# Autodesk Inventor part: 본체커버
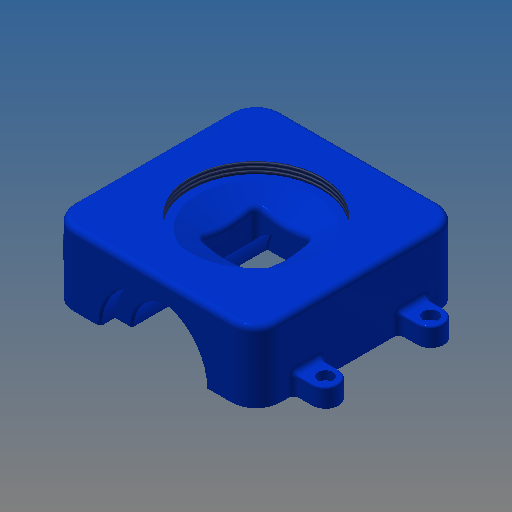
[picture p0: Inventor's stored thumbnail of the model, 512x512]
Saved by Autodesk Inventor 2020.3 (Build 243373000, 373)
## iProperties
Created: 2018-01
Part Number: 본체커버
Material: 알루미늄 6061
Document SubType Name: Modeling
Designer: mduedu
Density: 1 g/cm^3
Appearance: 선명 - 파란색
Author: mduedu
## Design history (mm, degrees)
sketch "스케치1"
  geometry: L1 (55, 55)-(-55, 55); L2 (-55, 55)-(-55, -55); L3 (-55, -55)-(55, -55); L4 (55, -55)-(55, 55); L5 (55, 55)-(-55, -55); L6 (-55, 55)-(55, -55); 1 further point
  constraints: 12 end point, 2 midpoint, 2 parallel, 1 horizontal, 1 perpendicular
  dimensions: "d0" = 110 distance of L3.end L2.end; "d1" = 110 distance of L2.end L1.end
extrude "돌출1" new body sketch "스케치1" distance "d2" = 38; taper "d3" = 0 deg
revolve "회전1" stored, may be unused: angle "d13" = 90 deg
fillet "모깎기1" dims "d14" = 1
fillet "모깎기2" dims "d15" = 13
fillet "모깎기3" dims "d16" = 3
sketch "스케치3"
  geometry: L1 (-15, -15)-(15, -15); L2 (15, -15)-(15, 15); L3 (15, 15)-(-15, 15); L4 (-15, 15)-(-15, -15); L5 (42, 55)-(-42, 55) reference; L6 (-15, -15)-(15, 15); L7 (15, -15)-(-15, 15); 2 further points
  constraints: 12 end point, 2 parallel, 1 horizontal, 1 midpoint, 1 perpendicular, 1 vertical alignment
  dimensions: "d19" = 30 distance of L3.end L1.start; "d20" = 30 distance between parallel lines of L2 L4; "d65" = 40 distance between parallel lines of L5 L3
extrude "돌출2" cut sketch "스케치3" extent not by distance; stored distance "d21" = 38; taper "d22" = 0 deg
fillet "모깎기4" dims "d23" = 3
sketch "스케치4"
  geometry: L1 (38, 35)-(32, 35); L2 (32, 35)-(32, 31); L3 (32, 31)-(25, 15); L4 (25, 15)-(25, 0); L5 (25, 0)-(38, 0); L6 (38, 0)-(38, 35); L7 (38, 42)-(38, -42) reference; 1 further point
  constraints: 12 end point, 2 parallel, 1 collinear, 1 horizontal, 1 horizontal alignment, 1 perpendicular
  dimensions: "d24" = 6 distance of L1.start L1.end; "d26" = 70 diameter of L1 L5; "d28" = 62 diameter of L2.end L5; "d29" = 30 diameter of L3.end L5; "d30" = 7 horizontal distance of L2.end L3.end
revolve "회전2" sketch "스케치4" stored, may be unused: angle "d31" = 90 deg
feature "스레드1" dims "d74" = 10, "d75" = 0
chamfer "모따기2" distance "d36" = 1; stored, may be unused: second distance "d37" = 2, angle "d38" = 45 deg
sketch "스케치5"
  geometry: L1 (-42, 55)-(-29, 55) reference; L2 (-55, -42)-(-55, 42) reference; L3 (42, -55)-(-42, -55) reference; L4 (55, 42)-(55, -42) reference; L5 (55, 35)-(65, 35); L6 (65, 21)-(55, 21); L7 (55, 21)-(55, 35); L8 (55, 42)-(55, -42) reference; L9 (28, 54)-(28, 47) reference; L10 (28, 47)-(20, 47) reference; L11 (19, 46)-(19, -24) reference; L12 (18, -25)-(7.5, -25) reference; L13 (7.5, -25)-(5.479, -28.5) reference; L14 (4.613, -29)-(-4.613, -29) reference; L15 (-5.479, -28.5)-(-7.5, -25) reference; L16 (-7.5, -25)-(-18, -25) reference; L17 (-19, -24)-(-19, 46) reference; L18 (-20, 47)-(-28, 47) reference; L19 (-28, 47)-(-28, 54) reference; L20 (19, 46)-(20, 47) reference; L21 (-20, 47)-(-19, 46) reference; L22 (-29, 55)-(-28, 54) reference; L23 (29, 55)-(42, 55) reference; L24 (28, 54)-(29, 55) reference; A1 r 13 centre (-42, 42) between (-42, 55) and (-55, 42) reference; A2 r 13 centre (-42, -42) between (-55, -42) and (-42, -55) reference; A3 r 13 centre (42, -42) between (42, -55) and (55, -42) reference; A4 r 13 centre (42, 42) between (55, 42) and (42, 55) reference; A5 r 7 centre (65, 28) between (65, 21) and (65, 35); A6 r 1 centre (18, -24) between (18, -25) and (19, -24) reference; A7 r 1 centre (4.613, -28) between (4.613, -29) and (5.479, -28.5) reference; A8 r 1 centre (-4.613, -28) between (-5.479, -28.5) and (-4.613, -29) reference; A9 r 1 centre (-18, -24) between (-19, -24) and (-18, -25) reference; 1 further point
  constraints: 6 end point, 2 point on circle, 2 tangent, 1 centre point, 1 collinear, 1 horizontal, 1 parallel, 1 point on line
  dimensions: "d39" = 14 distance between parallel lines of L6 L5; "d41" = 28 vertical distance of A5.centre point (0, 0); "d42" = 10 distance from line of A5.centre L4
extrude "돌출3" join sketch "스케치5" distance "d43" = 10; taper "d44" = 0 deg
fillet "모깎기6" dims "d45" = 1
fillet "모깎기7" dims "d46" = 3
sketch "스케치6"
  geometry: A1 r 7 centre (-65, 28) between (-65, 35) and (-65, 21) reference; A2 r 7 centre (-65, -28) between (-65, -21) and (-65, -35) reference; A3 r 7 centre (65, -28) between (65, -35) and (65, -21) reference; A4 r 7 centre (65, 28) between (65, 21) and (65, 35) reference; 5 further points
  constraints: 4 coincident
sketch "스케치7"
  geometry: 4 further points
  constraints: 4 other
hole "구멍1" sketch "스케치7" at (-65, 28), (65, 28), (-65, -28), (65, -28) diameter "d47" = 4.5; stored, may be unused: countersink angle "d51" = 90 deg, drill point angle "d53" = 0 deg; dims "d48" = 6, "d49" = 8, "d50" = 4.6, "d52" = 8
sketch "스케치9" dims "d66" = 46
  geometry: 3 further points
  constraints: 2 vertical alignment, 1 coincident, 2 other
hole "구멍2" sketch "스케치9" at (0, 23) diameter "d67" = 3.242; stored, may be unused: countersink angle "d71" = 90 deg, drill point angle "d73" = 118 deg; dims "d68" = 9, "d69" = 4, "d70" = 2, "d72" = 11
sketch "스케치8"
  geometry: L1 (-97, 35)-(-97, 0) reference; L2 (0, 38)-(-84, 38) reference; 2 further points
  constraints: 1 other
  dimensions: "d54" = 55 distance from line of point (-42, 23) L1; "d55" = 15 distance from line of point (-42, 23) L2
feature "엠보싱1" sketch "스케치8" dims "d0" = 110, "d1" = 110, "d56" = 0.5, "d57" = 0
node "솔리드1"
mirror "대칭1"
mirror "대칭2"
sketch "스케치2"
  geometry: L1 (-55, 55)-(55, 55) reference; L2 (-55, -55)-(-55, 55) reference; L3 (55, -55)-(-55, -55) reference; L4 (55, 55)-(55, -55) reference; L5 (0, 55)-(28, 55); L6 (19, 47)-(19, -25); L7 (19, -25)-(7.5, -25); L8 (0, -25.854)-(0, 55); L9 (7.5, -25)-(5.191, -29); L10 (5.191, -29)-(0, -29); L11 (0, -29)-(0, -25.854); L12 (19, 47)-(28, 47); L13 (28, 47)-(28, 55); 1 further point
  constraints: 18 end point, 2 horizontal, 2 perpendicular, 1 midpoint, 1 parallel, 1 point on line, 1 vertical
  dimensions: "d7" = 38 diameter of L6 L8; "d58" = 4 distance between parallel lines of L7 L10; "d59" = 30 deg angle of L8 L9; "d60" = 15 diameter of L7.end L8; "d61" = 56 diameter of L13 L8; "d62" = 8 distance of L12.end L5.end; "d63" = 84 distance between parallel lines of L10 L5
node "투영된 루프1"
node "투영된 루프2"
